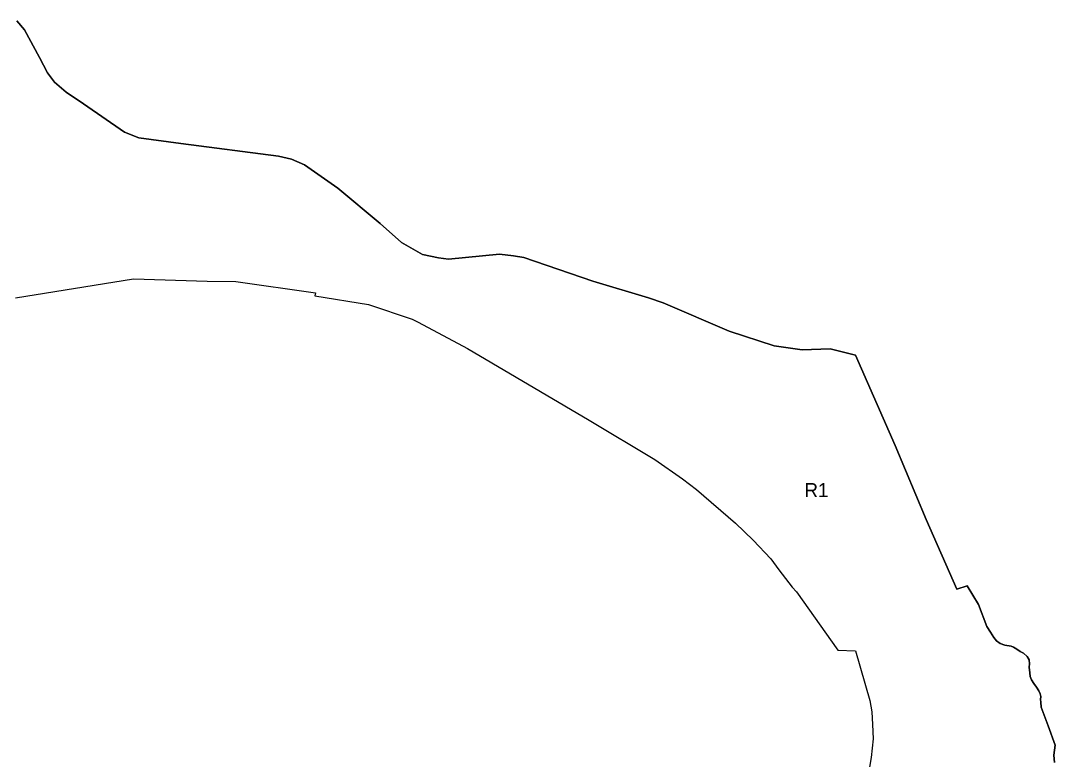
# Model space of a CAD drawing. Extents: x 7428103 to 7431580, y 5545880 to 5549002.
# Drawn here: x 7430624.7 to 7431034.6, y 5547815.6 to 5548108.2 of the extents above; entities that cross this region are included whole.
import ezdxf

# ---------------------------------------------------------------- set-up
doc = ezdxf.new("R2010")
doc.units = 0
for name, color, linetype in [('CZ_L_granica obszaru objętego planem', 7, 'Continuous'), ('CZ_L_linie rozgraniczające tereny o różnym przeznaczeniu oraz różnych warunkach ich zabudowy i zagospodarowania', 7, 'Continuous'), ('CZ_L_opisy_linie rozgraniczające tereny o różnym przeznaczeniu oraz różnych warunkach ich zabudowy i zagospodarowania', 7, 'Continuous'), ('Łąki_Nowohuckie', 7, 'Continuous')]:
    doc.layers.add(name, color=color, linetype=linetype)

msp = doc.modelspace()

# ---------------------------------------------------------------- linework, layer by layer
at = {"layer": 'CZ_L_granica obszaru objętego planem'}
for p, q in [((7430623.24, 5548108.21), (7430626.18, 5548104.53)), ((7430626.18, 5548104.53), (7430632.12, 5548093.62)), ((7430632.12, 5548093.62), (7430635.33, 5548087.54)), ((7430635.33, 5548087.54), (7430638.13, 5548083.85)), ((7430638.13, 5548083.85), (7430642.68, 5548079.88)), ((7430642.68, 5548079.88), (7430649.53, 5548075.24)), ((7430649.53, 5548075.24), (7430665.79, 5548064.12)), ((7430665.79, 5548064.12), (7430671.47, 5548061.79)), ((7430671.47, 5548061.79), (7430688.19, 5548059.53)), ((7430688.19, 5548059.53), (7430726.82, 5548054.52)), ((7430726.82, 5548054.52), (7430732.02, 5548053.36)), ((7430732.02, 5548053.36), (7430737.12, 5548051.07)), ((7430737.12, 5548051.07), (7430750.4, 5548041.92)), ((7430750.4, 5548041.92), (7430767.09, 5548027.83)), ((7430767.09, 5548027.83), (7430775.62, 5548020.33)), ((7430775.62, 5548020.33), (7430783.88, 5548015.57)), ((7430783.88, 5548015.57), (7430790.22, 5548014.32)), ((7430790.22, 5548014.32), (7430794.17, 5548013.75)), ((7430794.17, 5548013.75), (7430814.42, 5548015.68)), ((7430814.42, 5548015.68), (7430819.96, 5548015.06)), ((7430819.96, 5548015.06), (7430824.01, 5548014.44)), ((7430824.01, 5548014.44), (7430851.36, 5548005.09)), ((7430851.36, 5548005.09), (7430873.39, 5547998.4)), ((7430873.39, 5547998.4), (7430879.3, 5547996.41)), ((7430879.3, 5547996.41), (7430905.38, 5547985.25)), ((7430905.38, 5547985.25), (7430923.19, 5547979.44)), ((7430923.19, 5547979.44), (7430934.35, 5547977.81)), ((7430934.35, 5547977.81), (7430945.37, 5547978.19)), ((7430945.37, 5547978.19), (7430955.48, 5547975.68)), ((7430955.48, 5547975.68), (7430971.11, 5547939.92)), ((7430971.11, 5547939.92), (7430983.49, 5547910.68)), ((7430983.49, 5547910.68), (7430995.55, 5547883)), ((7430995.55, 5547883), (7430999.65, 5547884.32)), ((7430999.65, 5547884.32), (7431004.24, 5547876.9)), ((7431004.24, 5547876.9), (7431007.47, 5547868.26)), ((7431007.47, 5547868.26), (7431009, 5547865.99)), ((7431009, 5547865.99), (7431010.33, 5547863.88)), ((7431010.33, 5547863.88), (7431011.3, 5547862.53)), ((7431011.3, 5547862.53), (7431012.73, 5547861.55)), ((7431012.73, 5547861.55), (7431014.61, 5547860.91)), ((7431014.61, 5547860.91), (7431017.16, 5547860.44)), ((7431017.16, 5547860.44), (7431018, 5547860)), ((7431018, 5547860), (7431019.32, 5547859.29)), ((7431019.32, 5547859.29), (7431020.64, 5547858.31)), ((7431020.64, 5547858.31), (7431022.06, 5547857.69)), ((7431022.06, 5547857.69), (7431023.5, 5547856.35)), ((7431023.5, 5547856.35), (7431024.23, 5547854.99)), ((7431024.23, 5547854.99), (7431024.39, 5547853.45)), ((7431024.39, 5547853.45), (7431024.29, 5547852.16)), ((7431024.29, 5547852.16), (7431024.53, 5547849.9)), ((7431024.53, 5547849.9), (7431024.64, 5547848.51)), ((7431024.64, 5547848.51), (7431025.2, 5547847.19)), ((7431025.2, 5547847.19), (7431026.08, 5547845.73)), ((7431026.08, 5547845.73), (7431027.13, 5547844.23)), ((7431027.13, 5547844.23), (7431028.05, 5547842.82)), ((7431028.05, 5547842.82), (7431028.61, 5547841.6)), ((7431028.61, 5547841.6), (7431028.86, 5547840.58)), ((7431028.86, 5547840.58), (7431028.8, 5547839.39)), ((7431028.8, 5547839.39), (7431028.85, 5547838.32)), ((7431028.85, 5547838.32), (7431028.98, 5547836.31)), ((7431028.98, 5547836.31), (7431031.74, 5547828.84)), ((7431031.74, 5547828.84), (7431034.62, 5547821.22)), ((7431034.62, 5547821.22), (7431034.05, 5547817.27)), ((7431034.05, 5547817.27), (7431034.37, 5547814.35))]:
    msp.add_line(p, q, dxfattribs=at)
at = {"layer": 'CZ_L_linie rozgraniczające tereny o różnym przeznaczeniu oraz różnych warunkach ich zabudowy i zagospodarowania'}
for p, q in [((7430622.64, 5547998.43), (7430669.36, 5548005.96)), ((7430669.36, 5548005.96), (7430698.57, 5548004.99)), ((7430698.57, 5548004.99), (7430709.98, 5548004.9)), ((7430709.98, 5548004.9), (7430741.52, 5548000.43)), ((7430741.52, 5548000.43), (7430741.3, 5547999.17)), ((7430741.3, 5547999.17), (7430762.5, 5547995.85)), ((7430762.5, 5547995.85), (7430779.77, 5547989.97)), ((7430779.77, 5547989.97), (7430782.18, 5547988.83)), ((7430782.18, 5547988.83), (7430801.68, 5547978.39)), ((7430801.68, 5547978.39), (7430849.88, 5547949.97)), ((7430849.88, 5547949.97), (7430875.98, 5547934.37)), ((7430875.98, 5547934.37), (7430886.9, 5547926.8)), ((7430886.9, 5547926.8), (7430892.48, 5547922.58)), ((7430892.48, 5547922.58), (7430907.91, 5547909.15)), ((7430907.91, 5547909.15), (7430914.98, 5547902.4)), ((7430914.98, 5547902.4), (7430921.92, 5547895.08)), ((7430921.92, 5547895.08), (7430925.14, 5547890.67)), ((7430925.14, 5547890.67), (7430930.31, 5547883.79)), ((7430930.31, 5547883.79), (7430932.08, 5547882.02)), ((7430932.08, 5547882.02), (7430948.5, 5547858.81)), ((7430948.5, 5547858.81), (7430955.47, 5547858.65)), ((7430955.47, 5547858.65), (7430961.18, 5547838.97)), ((7430961.18, 5547838.97), (7430961.87, 5547834.46)), ((7430961.87, 5547834.46), (7430962.23, 5547829.37)), ((7430962.23, 5547829.37), (7430962.4, 5547823.76)), ((7430962.4, 5547823.76), (7430961.7, 5547816.41)), ((7430961.7, 5547816.41), (7430954.88, 5547778.35))]:
    msp.add_line(p, q, dxfattribs=at)
msp.add_lwpolyline([(7430623.24, 5548108.21), (7430626.18, 5548104.53), (7430632.12, 5548093.62), (7430635.33, 5548087.54), (7430638.13, 5548083.85), (7430642.68, 5548079.88), (7430649.53, 5548075.24), (7430665.79, 5548064.12), (7430671.47, 5548061.79), (7430688.19, 5548059.53), (7430726.82, 5548054.52), (7430732.02, 5548053.36), (7430737.12, 5548051.07), (7430750.4, 5548041.92), (7430767.09, 5548027.83), (7430775.62, 5548020.33), (7430783.88, 5548015.57), (7430790.22, 5548014.32), (7430794.17, 5548013.75), (7430814.42, 5548015.68), (7430819.96, 5548015.06), (7430824.01, 5548014.44), (7430851.36, 5548005.09), (7430873.39, 5547998.4), (7430879.3, 5547996.41), (7430905.38, 5547985.25), (7430923.19, 5547979.44), (7430934.35, 5547977.81), (7430945.37, 5547978.19), (7430955.48, 5547975.68), (7430971.11, 5547939.92), (7430983.49, 5547910.68), (7430995.55, 5547883), (7430999.65, 5547884.32), (7431004.24, 5547876.9), (7431007.47, 5547868.26), (7431009, 5547865.99), (7431010.33, 5547863.88), (7431011.3, 5547862.53), (7431012.73, 5547861.55), (7431014.61, 5547860.91), (7431017.16, 5547860.44), (7431018, 5547860), (7431019.32, 5547859.29), (7431020.64, 5547858.31), (7431022.06, 5547857.69), (7431023.5, 5547856.35), (7431024.23, 5547854.99), (7431024.39, 5547853.45), (7431024.29, 5547852.16), (7431024.53, 5547849.9), (7431024.64, 5547848.51), (7431025.2, 5547847.19), (7431026.08, 5547845.73), (7431027.13, 5547844.23), (7431028.05, 5547842.82), (7431028.61, 5547841.6), (7431028.86, 5547840.58), (7431028.8, 5547839.39), (7431028.85, 5547838.32), (7431028.98, 5547836.31), (7431031.74, 5547828.84), (7431034.62, 5547821.22), (7431034.05, 5547817.27), (7431034.37, 5547814.35)], dxfattribs=at)
at = {"layer": 'Łąki_Nowohuckie'}
for p, q in [((7430626.18, 5548104.53), (7430623.24, 5548108.21)), ((7430632.12, 5548093.62), (7430626.18, 5548104.53)), ((7430635.33, 5548087.54), (7430632.12, 5548093.62)), ((7430638.13, 5548083.85), (7430635.33, 5548087.54)), ((7430642.68, 5548079.88), (7430638.13, 5548083.85)), ((7430649.53, 5548075.24), (7430642.68, 5548079.88)), ((7430665.79, 5548064.12), (7430649.53, 5548075.24)), ((7430671.47, 5548061.79), (7430665.79, 5548064.12)), ((7430688.19, 5548059.53), (7430671.47, 5548061.79)), ((7430726.82, 5548054.52), (7430688.19, 5548059.53)), ((7430732.02, 5548053.36), (7430726.82, 5548054.52)), ((7430737.12, 5548051.07), (7430732.02, 5548053.36)), ((7430750.4, 5548041.92), (7430737.12, 5548051.07)), ((7430767.09, 5548027.83), (7430750.4, 5548041.92)), ((7430775.62, 5548020.33), (7430767.09, 5548027.83)), ((7430783.88, 5548015.57), (7430775.62, 5548020.33)), ((7430790.22, 5548014.32), (7430783.88, 5548015.57)), ((7430794.17, 5548013.75), (7430790.22, 5548014.32)), ((7430814.42, 5548015.68), (7430794.17, 5548013.75)), ((7430819.96, 5548015.06), (7430814.42, 5548015.68)), ((7430824.01, 5548014.44), (7430819.96, 5548015.06)), ((7430851.36, 5548005.09), (7430824.01, 5548014.44)), ((7430873.39, 5547998.4), (7430851.36, 5548005.09)), ((7430879.3, 5547996.41), (7430873.39, 5547998.4)), ((7430905.38, 5547985.25), (7430879.3, 5547996.41)), ((7430923.19, 5547979.44), (7430905.38, 5547985.25)), ((7430934.35, 5547977.81), (7430923.19, 5547979.44)), ((7430945.37, 5547978.19), (7430934.35, 5547977.81)), ((7430955.48, 5547975.68), (7430945.37, 5547978.19)), ((7430971.11, 5547939.92), (7430955.48, 5547975.68)), ((7430983.49, 5547910.68), (7430971.11, 5547939.92)), ((7430995.55, 5547883), (7430983.49, 5547910.68)), ((7430999.65, 5547884.32), (7430995.55, 5547883)), ((7431004.24, 5547876.9), (7430999.65, 5547884.32)), ((7431007.47, 5547868.26), (7431004.24, 5547876.9)), ((7431009, 5547865.99), (7431007.47, 5547868.26)), ((7431010.33, 5547863.88), (7431009, 5547865.99)), ((7431011.3, 5547862.53), (7431010.33, 5547863.88)), ((7431012.73, 5547861.55), (7431011.3, 5547862.53)), ((7431014.61, 5547860.91), (7431012.73, 5547861.55)), ((7431017.16, 5547860.44), (7431014.61, 5547860.91)), ((7431018, 5547860), (7431017.16, 5547860.44)), ((7431019.32, 5547859.29), (7431018, 5547860)), ((7431020.64, 5547858.31), (7431019.32, 5547859.29)), ((7431022.06, 5547857.69), (7431020.64, 5547858.31)), ((7431023.5, 5547856.35), (7431022.06, 5547857.69)), ((7431024.23, 5547854.99), (7431023.5, 5547856.35)), ((7431024.39, 5547853.45), (7431024.23, 5547854.99)), ((7431024.29, 5547852.16), (7431024.39, 5547853.45)), ((7431024.53, 5547849.9), (7431024.29, 5547852.16)), ((7431024.64, 5547848.51), (7431024.53, 5547849.9)), ((7431025.2, 5547847.19), (7431024.64, 5547848.51)), ((7431026.08, 5547845.73), (7431025.2, 5547847.19)), ((7431027.13, 5547844.23), (7431026.08, 5547845.73)), ((7431028.05, 5547842.82), (7431027.13, 5547844.23)), ((7431028.61, 5547841.6), (7431028.05, 5547842.82)), ((7431028.86, 5547840.58), (7431028.61, 5547841.6)), ((7431028.8, 5547839.39), (7431028.86, 5547840.58)), ((7431028.85, 5547838.32), (7431028.8, 5547839.39)), ((7431028.98, 5547836.31), (7431028.85, 5547838.32)), ((7431031.74, 5547828.84), (7431028.98, 5547836.31)), ((7431034.62, 5547821.22), (7431031.74, 5547828.84)), ((7431034.05, 5547817.27), (7431034.62, 5547821.22)), ((7431034.37, 5547814.35), (7431034.05, 5547817.27))]:
    msp.add_line(p, q, dxfattribs=at)

# ---------------------------------------------------------------- texts
at = {"layer": 'CZ_L_opisy_linie rozgraniczające tereny o różnym przeznaczeniu oraz różnych warunkach ich zabudowy i zagospodarowania'}
msp.add_text('R1', height=5.549, dxfattribs=at).set_placement((7430935.25, 5547919.52))

doc.saveas('drawing.dxf')
